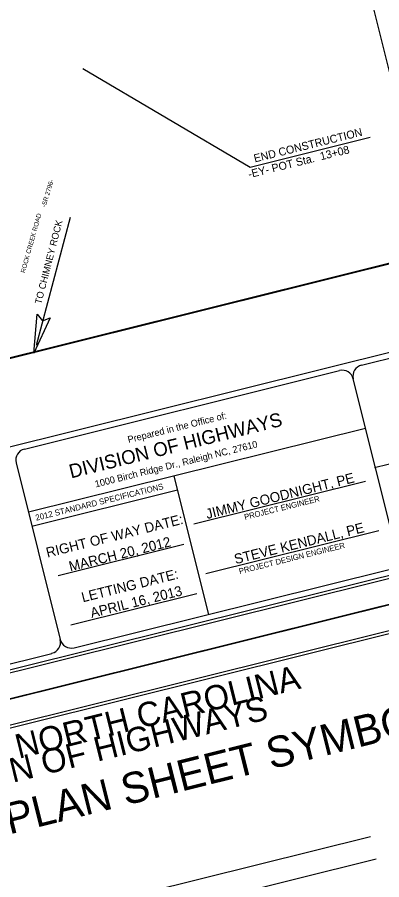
# Model space of a CAD drawing. Extents: x 1030323 to 1034123, y 654802 to 657751.
# Drawn here: x 1031475 to 1031795, y 655929 to 656687 of the extents above; entities that cross this region are included whole.
import ezdxf

# ---------------------------------------------------------------- set-up
doc = ezdxf.new("R2010")
doc.units = 0
for name, color, linetype in [('Old_Level_1', 7, 'Continuous'), ('Prop Horizontal Alignment Station Label', 7, 'Continuous'), ('Prop Terminator CELL', 7, 'Continuous'), ('Sheet Clip Boundary CELL', 7, 'Continuous'), ('Sheet Cutting Line CELL', 7, 'Continuous'), ('Sheet Data Field CELL', 7, 'Continuous'), ('Sheet Plot Border Inside CELL', 7, 'Continuous'), ('Sheet Plot Border Outside CELL', 7, 'Continuous'), ('Sheet Symbology CELL', 7, 'Continuous'), ('Sheet Title CELL', 7, 'Continuous')]:
    doc.layers.add(name, color=color, linetype=linetype)

msp = doc.modelspace()

# ---------------------------------------------------------------- linework, layer by layer
at = {"layer": 'Old_Level_1'}
msp.add_line((1031521.55, 656511.47), (1031491.72, 656398.99), dxfattribs=at)
at = {"layer": 'Prop Horizontal Alignment Station Label'}
for p, q in [((1031532.57, 656642.46), (1031679.65, 656555.88)), ((1031679.65, 656555.88), (1031784.83, 656582.1))]:
    msp.add_line(p, q, dxfattribs=at)
at = {"layer": 'Prop Terminator CELL'}
msp.add_lwpolyline([(1031504.08, 656423.32), (1031489.81, 656392.18), (1031492.71, 656426.52), (1031497.41, 656420.82)], close=True, dxfattribs=at)
at = {"layer": 'Sheet Clip Boundary CELL'}
msp.add_lwpolyline([(1031088.75, 656293.37), (1030994.11, 656269.56), (1030843.5, 656511.74), (1030969.21, 656567.19), (1030968.58, 656775.34), (1031272.57, 656874.34), (1031522.82, 656933.1), (1031562.8, 656947.62), (1031759.53, 656972.55), (1031879.7, 656490.58)], close=True, dxfattribs=at)
at = {"layer": 'Sheet Cutting Line CELL'}
for p, q in [((1030589.1, 655869.05), (1032223.08, 656276.44)), ((1032223.08, 656276.44), (1030589.1, 655869.05))]:
    msp.add_line(p, q, dxfattribs=at)
at = {"layer": 'Sheet Plot Border Inside CELL'}
for points in [[(1030596.28, 655893.96), (1032213.28, 656297.13), (1031958.03, 657320.89), (1030341.03, 656917.72)], [(1030862.39, 654826.65), (1032479.39, 655229.81), (1032224.14, 656253.57), (1030607.14, 655850.41)]]:
    msp.add_lwpolyline(points, close=True, dxfattribs=at)
at = {"layer": 'Sheet Plot Border Outside CELL'}
for points in [[(1031956.96, 657343.76), (1030322.99, 656936.36), (1030589.1, 655869.05), (1032223.08, 656276.44)], [(1030855.21, 654801.72), (1032489.19, 655209.12), (1032223.08, 656276.44), (1030589.1, 655869.05)]]:
    msp.add_lwpolyline(points, close=True, dxfattribs=at)
at = {"layer": 'Sheet Symbology CELL'}
for p, q in [((1031785.23, 655967.11), (1031586.38, 655917.54)), ((1031790.07, 655947.71), (1031591.22, 655898.13))]:
    msp.add_line(p, q, dxfattribs=at)
msp.add_lwpolyline([(1032212.63, 656248.07), (1030757.19, 655885.19), (1031010.96, 654867.37), (1032466.4, 655230.25)], close=True, dxfattribs=at)
at = {"layer": 'Sheet Title CELL'}
for p, q in [((1030762.19, 656133.79), (1032140.01, 656477.32)), ((1031777.36, 656381.74), (1031971.2, 656430.07)), ((1031481.42, 656307.96), (1031757.96, 656376.91)), ((1031808.79, 656214.36), (1031770.08, 656369.61)), ((1031788.55, 656291.8), (1032002.67, 656345.19)), ((1031780.91, 656326.19), (1031484.96, 656252.42)), ((1031474.14, 656295.84), (1031512.85, 656140.59)), ((1031612.61, 656284.24), (1031642.91, 656162.71)), ((1031630.19, 656242.25), (1031780.73, 656279.77)), ((1031615.69, 656271.86), (1031488.05, 656240.04)), ((1031578.92, 656262.7), (1031578.92, 656262.7)), ((1031640.73, 656198.5), (1031792.34, 656236.3)), ((1031621.44, 656223.99), (1031511.07, 656196.47)), ((1031566.24, 656210.21), (1031566.24, 656210.21)), ((1031632.62, 656180.81), (1031522.25, 656153.29))]:
    msp.add_line(p, q, dxfattribs=at)
for points in [[(1031755.78, 656823), (1031841.22, 656480.34), (1031050.26, 656283.14), (1030953.9, 656669.65)], [(1030754.79, 655936.11), (1032190.83, 656294.16)], [(1031524.97, 656133.31), (1031801.5, 656202.24)], [(1031136.85, 656036.52), (1031505.56, 656128.45)]]:
    msp.add_lwpolyline(points, dxfattribs=at)
for centre, start, end in [((1031779.77, 656372.09), 104, 194), ((1031760.37, 656367.25), 14, 104), ((1031483.83, 656298.3), 104, 194), ((1031503.14, 656138.21), 284, 14), ((1031522.54, 656143.05), 194, 284)]:
    msp.add_arc(centre, 10, start, end, dxfattribs=at)

# ---------------------------------------------------------------- texts
at = {"layer": 'Old_Level_1'}
for s, height, rotation, p in [('-SR 2796-', 4, 73.14215, (1031499.99, 656520.12)), ('ROCK CREEK ROAD', 4, 74.46466, (1031481.89, 656462.43)), ('TO CHIMNEY ROCK', 6, 75.67829, (1031496.23, 656434.93))]:
    msp.add_text(s, height=height, rotation=rotation, dxfattribs=at).set_placement(p)
at = {"layer": 'Prop Horizontal Alignment Station Label'}
for s, p in [('END CONSTRUCTION', (1031683.67, 656559.88)), ('-EY- POT Sta.  13+08', (1031678.68, 656546.01))]:
    msp.add_text(s, height=7, rotation=14, dxfattribs=at).set_placement(p)
at = {"layer": 'Sheet Data Field CELL'}
for s, p in [('JIMMY GOODNIGHT, PE', (1031641.8, 656246.47)), ('STEVE KENDALL, PE', (1031666.79, 656206.81)), ('MARCH 20, 2012', (1031521.71, 656200.44)), ('APRIL 16, 2013', (1031540.48, 656159.58))]:
    msp.add_text(s, height=8.7501, rotation=14, dxfattribs=at).set_placement(p)
at = {"layer": 'Sheet Symbology CELL'}
for s, height, p in [('STATE OF NORTH CAROLINA', 21.419, (1031332.83, 655999.9)), ('CONVENTIONAL  PLAN SHEET SYMBOLS', 27.2003, (1031170.08, 655894.92)), ('DIVISION OF HIGHWAYS', 21.419, (1031369.34, 655989.25))]:
    msp.add_text(s, height=height, rotation=14, dxfattribs=at).set_placement(p)
at = {"layer": 'Sheet Title CELL'}
for s, height, p in [('DIVISION OF HIGHWAYS', 12.1872, (1031522.37, 656282.15)), ('Prepared in the Office of:', 5.9994, (1031572.85, 656313.27)), ('1000 Birch Ridge Dr., Raleigh NC, 27610', 6, (1031544.11, 656274.22)), ('2012 STANDARD SPECIFICATIONS', 5.2, (1031491.82, 656244.95)), ('PROJECT ENGINEER', 4.9995, (1031675.03, 656245.7)), ('RIGHT OF WAY DATE: ', 8.7498, (1031501.65, 656212.57)), ('PROJECT DESIGN ENGINEER', 4.9995, (1031670.41, 656198.1)), ('LETTING DATE:', 8.7498, (1031532.73, 656173.27))]:
    msp.add_text(s, height=height, rotation=14, dxfattribs=at).set_placement(p)

doc.saveas('drawing.dxf')
